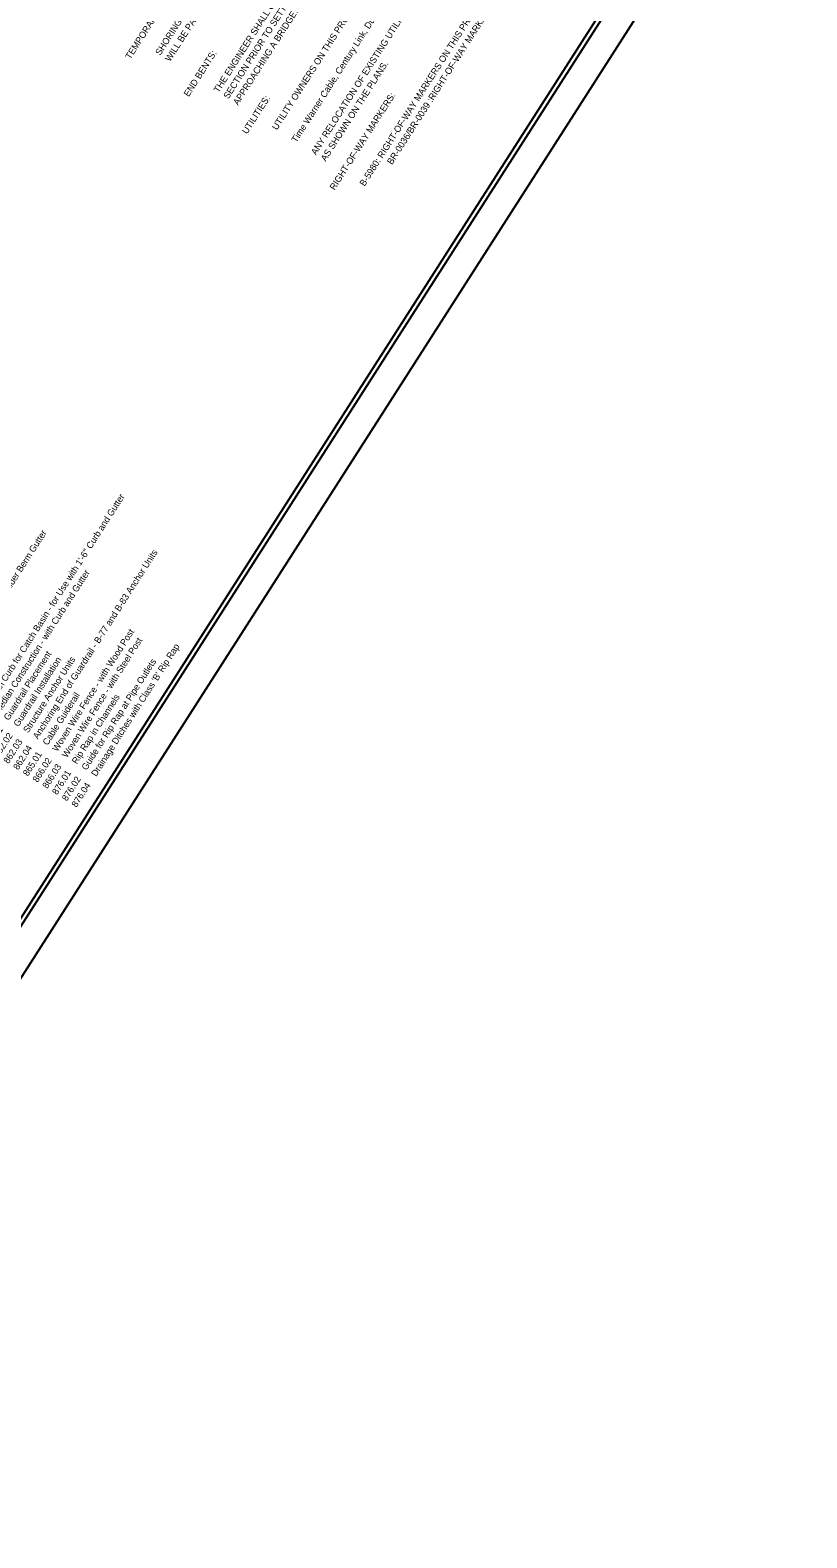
# Model space of a CAD drawing. Extents: x 2347249 to 2361994, y 830101 to 846299.
# Drawn here: x 2357017 to 2361994, y 830101 to 839761 of the extents above; entities that cross this region are included whole.
import ezdxf

# ---------------------------------------------------------------- set-up
doc = ezdxf.new("R2010")
doc.units = 0
for name, color, linetype in [('Sheet Data Field CELL', 7, 'Continuous'), ('Sheet Plot Border Inside CELL', 7, 'Continuous'), ('Sheet Plot Border Outside CELL', 7, 'Continuous'), ('Sheet Symbology CELL', 7, 'Continuous')]:
    doc.layers.add(name, color=color, linetype=linetype)

msp = doc.modelspace()

# ---------------------------------------------------------------- linework, layer by layer
at = {"layer": 'Sheet Plot Border Inside CELL'}
msp.add_lwpolyline([(2354564.1, 830285.9), (2361823.6, 841618.9), (2354715.9, 846171.7), (2347456.5, 834838.7)], close=True, dxfattribs=at)
at = {"layer": 'Sheet Plot Border Outside CELL'}
msp.add_lwpolyline([(2354658.7, 830100.6), (2361994.4, 841552.6), (2354584.3, 846299.2), (2347248.6, 834847.2)], close=True, dxfattribs=at)
at = {"layer": 'Sheet Symbology CELL'}
msp.add_lwpolyline([(2354678.6, 846075.7), (2348144.5, 835875), (2355211, 831348.5), (2361745.1, 841549.2)], close=True, dxfattribs=at)

# ---------------------------------------------------------------- texts
at = {"layer": 'Sheet Data Field CELL'}
for s, p in [('        SHORING REQUIRED FOR THE MAINTENANCE OF TRAFFIC NOT SHOWN ON THE PLANS ', (2357783.7, 839490.4)), ('        SECTION PRIOR TO SETTING OF THE SLOPE STAKES FOR THE EMBANKMENT OR EXCAVATION ', (2358219.9, 839211)), ('        THE ENGINEER SHALL CHECK THE STRUCTURE END BENT PLANS, DETAILS, AND CROSS-', (2358157.6, 839250.9)), ('        WILL BE PAID FOR AT THE CONTRACT PRICE FOR "TEMPORARY SHORING".', (2357846, 839450.5)), ('BR-0036/BR-0039 :RIGHT-OF-WAY MARKERS ON THIS PROJECT SHALL BE PLACED BY THE STATE.  ', (2359336, 838895.1)), ('        ANY RELOCATION OF EXISTING UTILITIES WILL BE ACCOMPLISHED BY OTHERS, EXCEPT ', (2358780.8, 838851.7)), ('        B-5980: RIGHT-OF-WAY MARKERS ON THIS PROJECT SHALL BE PLACED BY CONTRACT.', (2359092.4, 838652.1)), ('        UTILITY OWNERS ON THIS PROJECT ARE  City of Rocky Mount, ', (2358531.5, 839011.4)), ('TEMPORARY SHORING:  ', (2357659, 839570.2)), ('        Time Warner Cable, Century Link, Duke Energy', (2358656.2, 838931.5)), ('        APPROACHING A BRIDGE.  ', (2358282.2, 839171)), ('END BENTS:  ', (2358033, 839330.7)), ('        AS SHOWN ON THE PLANS.  ', (2358843.1, 838811.8)), ('UTILITIES:  ', (2358406.9, 839091.2)), ('RIGHT-OF-WAY MARKERS:  ', (2358967.8, 838731.9)), ('852.05    Median Curb for Catch Basin - for Use with 1\'-6" Curb and Gutter', (2356628.3, 835216.9)), ('846.04    Drop Inlet Installation in Shoulder Berm Gutter', (2356379, 835376.6)), ('862.04    Anchoring End of Guardrail - B-77 and B-83 Anchor Units', (2356939.9, 835017.3)), ('852.10    Median Construction - with Curb and Gutter', (2356690.6, 835177)), ('866.02    Woven Wire Fence - with Wood Post', (2357064.5, 834937.4)), ('866.03    Woven Wire Fence - with Steel Post', (2357126.8, 834897.5)), ("876.04    Drainage Ditches with Class 'B' Rip Rap", (2357313.8, 834777.8)), ('862.01    Guardrail Placement', (2356752.9, 835137)), ('862.02    Guardrail Installation', (2356815.2, 835097.1)), ('862.03    Structure Anchor Units', (2356877.6, 835057.2)), ('876.02    Guide for Rip Rap at Pipe Outlets', (2357251.5, 834817.7)), ('865.01    Cable Guiderail', (2357002.2, 834977.4)), ('876.01    Rip Rap in Channels', (2357189.2, 834857.6))]:
    msp.add_text(s, height=42, rotation=57.35811, dxfattribs=at).set_placement(p)

doc.saveas('drawing.dxf')
